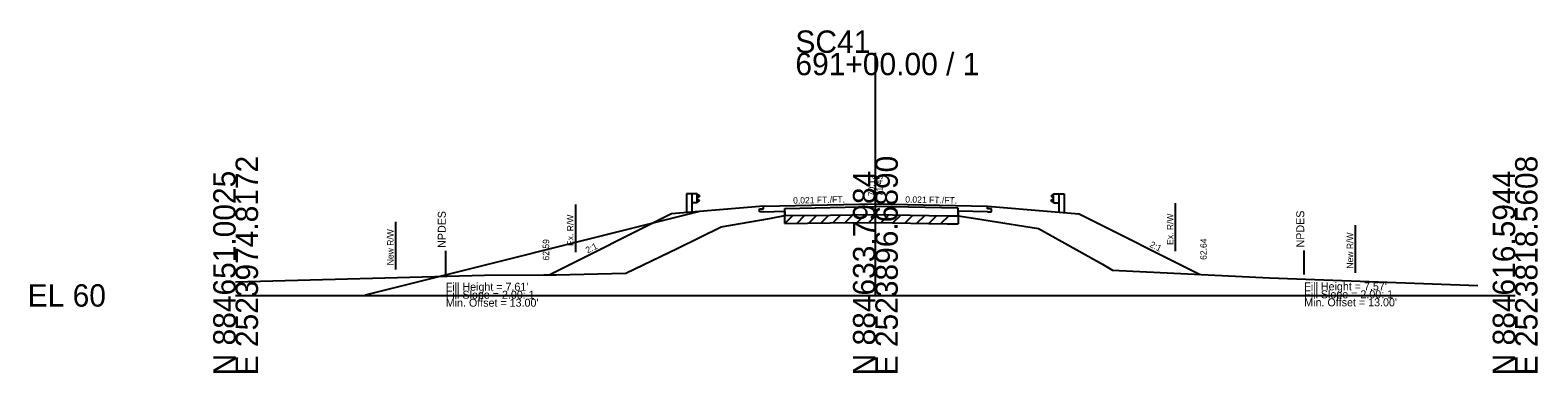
# Model space of a CAD drawing. Extents: x -26 to 183, y -10 to 24021.
# Drawn here: x -25.7 to 162.8, y 17490.3 to 17533.2 of the extents above; entities that cross this region are included whole.
import ezdxf

# ---------------------------------------------------------------- set-up
doc = ezdxf.new("R2010")
doc.units = 0
for name, color, linetype in [('RD_GPK_XS_Cell', 7, 'Continuous'), ('RD_XS_Base', 7, 'Continuous'), ('RD_XS_Buildup', 7, 'Continuous'), ('RD_XS_EarthShd', 7, 'Continuous'), ('RD_XS_ExGround', 7, 'Continuous'), ('RD_XS_ExPaveRet', 7, 'Continuous'), ('RD_XS_ExRW', 7, 'Continuous'), ('RD_XS_GR', 7, 'Continuous'), ('RD_XS_NewRW', 7, 'Continuous'), ('RD_XS_NPDES', 7, 'Continuous'), ('RD_XS_Pave', 7, 'Continuous'), ('RD_XS_TieSlope', 7, 'Continuous'), ('RD_XS_TX_Elev_EX', 7, 'Continuous'), ('RD_XS_TX_Elev_PR', 7, 'Continuous'), ('RD_XS_TX_Slope', 7, 'Continuous'), ('RD_XS_TX_Warning', 7, 'Continuous')]:
    doc.layers.add(name, color=color, linetype=linetype)

msp = doc.modelspace()

# ---------------------------------------------------------------- linework, layer by layer
at = {"layer": 'RD_GPK_XS_Cell'}
for p, q in [((80, 17500), (80, 17530.37)), ((0, 17500), (80, 17500)), ((80, 17500), (160, 17500))]:
    msp.add_line(p, q, dxfattribs=at)
at = {"layer": 'RD_XS_Base'}
for p, q in [((66, 17510.48), (68.68, 17510.54)), ((68.68, 17510.54), (68.68, 17510.01)), ((90.35, 17510.56), (90.35, 17509.95)), ((94, 17510.48), (90.35, 17510.56))]:
    msp.add_line(p, q, dxfattribs=at)
at = {"layer": 'RD_XS_Buildup'}
for p, q in [((68.68, 17510.9), (80, 17511.13)), ((90.35, 17510.92), (80, 17511.13)), ((90.35, 17509.95), (90.35, 17510.92)), ((68.68, 17510.01), (68.68, 17510.9))]:
    msp.add_line(p, q, dxfattribs=at)
at = {"layer": 'RD_XS_EarthShd'}
for p, q in [((66, 17511.16), (58, 17510.49)), ((94, 17511.16), (102, 17510.49)), ((58, 17510.49), (54.5, 17510.2)), ((102, 17510.49), (105.5, 17510.2))]:
    msp.add_line(p, q, dxfattribs=at)
at = {"layer": 'RD_XS_ExGround'}
for p, q in [((60.72, 17508.57), (66.76, 17509.65)), ((66.76, 17509.65), (68.68, 17510.01)), ((68.68, 17510.01), (74.35, 17510.07)), ((74.35, 17510.07), (79.85, 17510.12)), ((79.85, 17510.12), (88.99, 17509.97)), ((88.99, 17509.97), (90.35, 17509.95)), ((90.35, 17509.95), (91.72, 17509.74)), ((91.72, 17509.74), (100.4, 17508.37)), ((55.3, 17505.93), (60.72, 17508.57)), ((100.4, 17508.37), (108.4, 17503.93)), ((48.78, 17502.8), (55.3, 17505.93)), ((108.4, 17503.93), (109.67, 17503.18)), ((0, 17501.71), (31.11, 17502.52)), ((31.11, 17502.52), (38.53, 17502.59)), ((38.53, 17502.59), (40.08, 17502.6)), ((40.08, 17502.6), (48.78, 17502.8)), ((109.67, 17503.18), (129.29, 17502.21)), ((129.29, 17502.21), (155.35, 17501.24))]:
    msp.add_line(p, q, dxfattribs=at)
at = {"layer": 'RD_XS_ExPaveRet'}
for p, q in [((68.68, 17509.01), (69.69, 17510.02)), ((68.68, 17509.01), (68.68, 17510.01)), ((68.68, 17509.01), (74.35, 17509.07)), ((70.18, 17509.02), (71.19, 17510.04)), ((71.68, 17509.04), (72.69, 17510.05)), ((73.18, 17509.06), (74.19, 17510.07)), ((74.35, 17509.07), (79.85, 17509.12)), ((74.68, 17509.08), (75.69, 17510.09)), ((76.18, 17509.09), (77.19, 17510.1)), ((77.68, 17509.1), (78.69, 17510.11)), ((79.18, 17509.12), (80.18, 17510.12)), ((79.85, 17509.12), (88.99, 17508.97)), ((80.68, 17509.11), (81.67, 17510.09)), ((82.18, 17509.09), (83.17, 17510.07)), ((83.68, 17509.06), (84.67, 17510.04)), ((85.18, 17509.04), (86.17, 17510.02)), ((86.68, 17509.01), (87.67, 17509.99)), ((88.18, 17508.99), (89.17, 17509.97)), ((90.35, 17509.95), (90.35, 17508.95)), ((88.99, 17508.97), (90.35, 17508.95))]:
    msp.add_line(p, q, dxfattribs=at)
at = {"layer": 'RD_XS_ExRW'}
for p, q in [((42.5, 17511.4), (42.5, 17505.4)), ((117.5, 17511.54), (117.5, 17505.54))]:
    msp.add_line(p, q, dxfattribs=at)
at = {"layer": 'RD_XS_GR'}
for p, q in [((56.4, 17512.74), (56.4, 17510.36)), ((57.06, 17512.74), (56.4, 17512.74)), ((57.06, 17512.74), (57.06, 17510.42)), ((57.73, 17512.74), (57.06, 17512.74)), ((57.73, 17511.58), (57.06, 17511.58)), ((57.73, 17511.58), (57.73, 17512.74)), ((57.73, 17512.67), (58, 17512.47)), ((58, 17512.42), (57.73, 17512.22)), ((58, 17511.9), (57.73, 17512.1)), ((57.73, 17511.65), (58, 17511.85)), ((58, 17512.47), (58, 17512.42)), ((58, 17511.85), (58, 17511.9)), ((102.27, 17512.67), (102, 17512.47)), ((102, 17512.47), (102, 17512.42)), ((102, 17512.42), (102.27, 17512.22)), ((102, 17511.9), (102.27, 17512.1)), ((102, 17511.85), (102, 17511.9)), ((102.27, 17511.65), (102, 17511.85)), ((102.27, 17512.74), (102.94, 17512.74)), ((102.27, 17511.58), (102.27, 17512.74)), ((102.27, 17511.58), (102.94, 17511.58)), ((102.94, 17512.74), (102.94, 17510.42)), ((102.94, 17512.74), (103.6, 17512.74)), ((103.6, 17512.74), (103.6, 17510.36))]:
    msp.add_line(p, q, dxfattribs=at)
at = {"layer": 'RD_XS_NewRW'}
for p, q in [((20, 17509.23), (20, 17503.23)), ((140, 17508.81), (140, 17502.81))]:
    msp.add_line(p, q, dxfattribs=at)
at = {"layer": 'RD_XS_NPDES'}
for p, q in [((26.28, 17502.59), (26.28, 17505.59)), ((133.63, 17502.64), (133.63, 17505.64))]:
    msp.add_line(p, q, dxfattribs=at)
at = {"layer": 'RD_XS_Pave'}
for p, q in [((66, 17511.16), (80, 17511.45)), ((66, 17510.84), (66, 17511.16)), ((80, 17511.45), (94, 17511.16)), ((94, 17510.84), (94, 17511.16)), ((58, 17510.49), (16.21, 17500.05)), ((65.5, 17510.83), (66, 17510.84)), ((65.5, 17510.47), (65.5, 17510.83)), ((66, 17510.48), (65.5, 17510.47)), ((94.5, 17510.83), (94, 17510.84)), ((94, 17510.48), (94.5, 17510.47)), ((94.5, 17510.47), (94.5, 17510.83))]:
    msp.add_line(p, q, dxfattribs=at)
at = {"layer": 'RD_XS_TieSlope'}
for p, q in [((54.5, 17510.2), (39.28, 17502.59)), ((105.5, 17510.2), (120.63, 17502.64))]:
    msp.add_line(p, q, dxfattribs=at)

# ---------------------------------------------------------------- texts
at = {"layer": 'RD_GPK_XS_Cell'}
for s, p in [('SC41', (70, 17530.37)), ('691+00.00 / 1', (70, 17527.57)), ('EL 60', (-26, 17498.6))]:
    msp.add_text(s, height=2.8, dxfattribs=at).set_placement(p)
for s, p in [('E 2523974.8172', (2.8, 17490)), ('E 2523896.6890', (82.8, 17490)), ('E 2523818.5608', (162.8, 17490)), ('N 884651.0025', (0, 17490)), ('N 884633.7984', (80, 17490)), ('N 884616.5944', (160, 17490))]:
    msp.add_text(s, height=2.8, rotation=90, dxfattribs=at).set_placement(p)
at = {"layer": 'RD_XS_ExRW'}
for p in [(42.25, 17506.19), (117.25, 17506.33)]:
    msp.add_text('Ex. R/W ', height=0.8, rotation=90, dxfattribs=at).set_placement(p)
at = {"layer": 'RD_XS_NewRW'}
for p in [(19.75, 17503.78), (139.75, 17503.36)]:
    msp.add_text('New R/W ', height=0.8, rotation=90, dxfattribs=at).set_placement(p)
at = {"layer": 'RD_XS_TX_Elev_EX'}
msp.add_text('70.12', height=0.8, rotation=90, dxfattribs=at).set_placement((79.9, 17512.42))
at = {"layer": 'RD_XS_TX_Elev_PR'}
for s, p in [('71.45', (80.9, 17512.42)), ('62.59', (39.21, 17504.37)), ('62.64', (121.43, 17504.45))]:
    msp.add_text(s, height=0.8, rotation=90, dxfattribs=at).set_placement(p)
at = {"layer": 'RD_XS_TX_Slope'}
for s, rotation, p in [('0.021 FT./FT.', 1.1916, (69.72, 17511.49)), ('0.021 FT./FT.', 358.8084, (83.73, 17511.63)), ('2:1', 26.5651, (44.01, 17505.24)), ('2:1', 333.4349, (114.22, 17506.12))]:
    msp.add_text(s, height=0.8, rotation=rotation, dxfattribs=at).set_placement(p)
at = {"layer": 'RD_XS_TX_Warning'}
for p in [(26.28, 17505.59), (133.63, 17505.64)]:
    msp.add_text(' NPDES', height=1, rotation=90, dxfattribs=at).set_placement(p)
for s, p in [("Fill Height = 7.61' ", (26.28, 17500.59)), ("Fill Height = 7.57' ", (133.63, 17500.64)), ('Fill Slope = 2.00: 1', (26.28, 17499.59)), ("Min. Offset = 13.00' ", (26.28, 17498.59)), ('Fill Slope = 2.00: 1', (133.63, 17499.64)), ("Min. Offset = 13.00' ", (133.63, 17498.64))]:
    msp.add_text(s, height=1, dxfattribs=at).set_placement(p)

doc.saveas('drawing.dxf')
